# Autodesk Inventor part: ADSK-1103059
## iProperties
Created: 2006-01
Part Number: ADSK-1103059
Document SubType Name: Modeling
Manufacturer: Standard
Standards Organization: Custom
Description: EXHAUST MANIFOLD
Mass: 4.07063 g
Surface Area: 55.5359 cm^2
Volume: 1.50208 cm^3
Density: 2.71 g/cm^3
Material: Aluminum-6061
Author: Autodesk, Inc.
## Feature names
1. Sweep1
2. Shell1
3. Revolution1
4. Fillet1
5. Fillet2
6. Fillet3
7. Extrusion1
8. Fillet4
